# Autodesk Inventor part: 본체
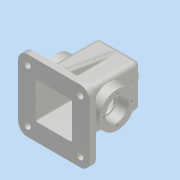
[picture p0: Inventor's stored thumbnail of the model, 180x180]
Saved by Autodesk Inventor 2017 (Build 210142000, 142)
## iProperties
Part Number: 본체
Material: 알루미늄 6061
Document SubType Name: Modeling
Designer: MRC
Density: 2.7 g/cm^3
Appearance: 알루미늄 - 평지
Mass: 753.623 g
Surface Area: 864.209 cm^2
Volume: 279.12 cm^3
Author: MRC
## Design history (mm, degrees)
sketch "스케치1"
  geometry: L1 (-34, 53)-(34, 53); L2 (34, 53)-(34, -52); L3 (34, -52)-(-34, -52); L4 (-34, -52)-(-34, 53); 2 further points
  constraints: 8 end point, 2 parallel, 1 horizontal, 1 midpoint, 1 perpendicular, 1 vertical alignment
  dimensions: "d2" = 68 distance of L2.end L3.end; "d3" = 105 distance of L1.end L2.end; "d4" = 52 distance of point (0, -52) point (0, 0)
extrude "돌출1" new body sketch "스케치1" stored distance "d5" = 68; taper "d6" = 0 deg
fillet "모깎기1" dims "d7" = 8
feature "쉘1" dims "d8" = 5
sketch "스케치2"
  geometry: C1 r 28.5 at (34, 52); 1 further point
  constraints: 1 centre point, 1 coincident
  dimensions: "d9" = 57 diameter of C1
extrude "돌출2" join sketch "스케치2" distance "d10" = 15; taper "d11" = 0 deg
sketch "스케치3"
  geometry: C1 r 28.5 at (0, 0) reference; 1 further point
  constraints: 1 coincident
hole "구멍1" sketch "스케치3" at (0, 0) diameter "d12" = 30; stored, may be unused: countersink angle "d16" = 90 deg, drill point angle "d18" = 0 deg; dims "d13" = 6, "d14" = 35, "d15" = 17, "d17" = 20
fillet "모깎기2" dims "d19" = 0.3
chamfer "모따기1" distance "d20" = 1; stored, may be unused: second distance "d21" = 2, angle "d22" = 45 deg
sketch "스케치4" dims "d23" = 44
  geometry: C1 r 18.5 at (0, 0) reference; 2 further points
  constraints: 1 coincident, 1 vertical alignment, 2 other
hole "구멍2" sketch "스케치4" at (0, 22) diameter "d24" = 3.242; stored, may be unused: countersink angle "d28" = 90 deg, drill point angle "d30" = 118 deg; dims "d25" = 8, "d26" = 35, "d27" = 17, "d29" = 10
fillet "모깎기4" dims "d35" = 0.3
chamfer "모따기2" distance "d36" = 1; stored, may be unused: second distance "d37" = 2, angle "d38" = 45 deg
sketch "스케치5"
  geometry: L1 (68, 0)-(68, -68) reference; L2 (0, 0)-(68, 0) reference; L3 (0, 0)-(0, -68) reference; L4 (68, -68)-(0, -68) reference; L5 (-23, -91)-(91, -91); L6 (91, -91)-(91, 23); L7 (91, 23)-(-23, 23); L8 (-23, 23)-(-23, -91); L9 (-23, -91)-(91, 23); L10 (91, -91)-(-23, 23); 1 further point
  constraints: 12 end point, 2 midpoint, 2 parallel, 1 horizontal, 1 perpendicular
  dimensions: "d40" = 114 distance of L7.end L6.end; "d41" = 114 distance of L6.end L5.end
extrude "돌출3" join sketch "스케치5" distance "d42" = 10; taper "d43" = 0 deg
fillet "모깎기6" dims "d44" = 15
sketch "스케치7"
  geometry: C1 r 20 at (26, -26); 1 further point
  constraints: 1 centre point, 1 coincident
  dimensions: "d47" = 40 diameter of C1
extrude "돌출4" join sketch "스케치7" distance "d48" = 10; taper "d49" = 0 deg
sketch "스케치8"
  geometry: C1 r 20 at (0, 0) reference; 1 further point
  constraints: 1 coincident
hole "구멍3" sketch "스케치8" at (0, 0) diameter "d50" = 22.835; stored, may be unused: countersink angle "d54" = 90 deg, drill point angle "d56" = 0 deg; dims "d51" = 50, "d52" = 35, "d53" = 17, "d55" = 59.3
sketch "스케치9"
  geometry: A1 r 15 centre (76, 76) between (91, 76) and (76, 91) reference; A2 r 15 centre (-8, 76) between (-8, 91) and (-23, 76) reference; A3 r 15 centre (-8, -8) between (-23, -8) and (-8, -23) reference; A4 r 15 centre (76, -8) between (76, -23) and (91, -8) reference; 5 further points
  constraints: 4 coincident
hole "구멍4" sketch "스케치9" at (76, -8), (-8, -8), (-8, 76), (76, 76) diameter "d57" = 10; stored, may be unused: countersink angle "d61" = 90 deg, drill point angle "d63" = 0 deg; dims "d58" = 50, "d59" = 18, "d60" = 2, "d62" = 59.3
sketch "스케치10"
  geometry: L1 (45, 29)-(-52, 29) reference; L2 (-52, 29)-(-52, 57) reference; L3 (-52, 57)-(-42, 57) reference; L4 (-42, 57)-(-42, 34) reference; L5 (-42, 34)-(45, 34) reference; L6 (53, 26)-(53, 20) reference; L7 (53, 20)-(63, 20) reference; L8 (63, 20)-(63, 11.418) reference; L9 (63, 11.418)-(48, 11.418) reference; L10 (48, 11.418)-(48, 26) reference; L11 (45, -34)-(-42, -34) reference; L12 (-42, -34)-(-42, -57) reference; L13 (-42, -57)-(-52, -57) reference; L14 (-52, -57)-(-52, -29) reference; L15 (-52, -29)-(45, -29) reference; L16 (48, -26)-(48, -11.418) reference; L17 (48, -11.418)-(63, -11.418) reference; L18 (63, -11.418)-(63, -20) reference; L19 (63, -20)-(53, -20) reference; L20 (53, -20)-(53, -26) reference; L21 (-6.124, 42.674)-(-42, 49); A1 r 3 centre (45, 26) between (48, 26) and (45, 29) reference; A2 r 8 centre (45, 26) between (53, 26) and (45, 34) reference; A3 r 8 centre (45, -26) between (45, -34) and (53, -26) reference; A4 r 3 centre (45, -26) between (45, -29) and (48, -26) reference; 1 further point
  constraints: 2 end point, 1 point on line
  dimensions: "d64" = 8 distance of L21.end L3.end; "d65" = 10 deg angle of L21 L3
feature "리브1" sketch "스케치10" dims "d66" = 1, "d67" = 10, "d68" = 0, "d69" = 0, "d70" = 1, "d71" = 1
fillet "모깎기7" dims "d72" = 8
fillet "모깎기8" dims "d73" = 3
fillet "모깎기9" dims "d74" = 3
fillet "모깎기10" dims "d75" = 3
fillet "모깎기11" dims "d76" = 3
fillet "모깎기12" dims "d77" = 3
fillet "모깎기13" dims "d78" = 3
sketch "스케치11"
  geometry: L1 (-8, 0)-(-8, -87) reference; L2 (46, 18)-(6, 18) reference; 1 further point
  constraints: 1 other
  dimensions: "d80" = 34 distance from line of L1 point (26, -7); "d81" = 25 distance from line of point (26, -7) L2
feature "엠보싱1" sketch "스케치11" dims "d82" = 0.5, "d83" = 0
fillet "모깎기15" dims "d84" = 3
fillet "모깎기16" dims "d85" = 3
fillet "모깎기17" dims "d86" = 3
feature "면 기울기1" dims angle "d87" = 8 deg
fillet "모깎기18" dims "d88" = 3
node "솔리드1"
pattern_circular "원형 패턴1" dims angle "d32" = 360 deg
mirror "미러1"
mirror "미러2"
node "절단 모서리 투영1"
